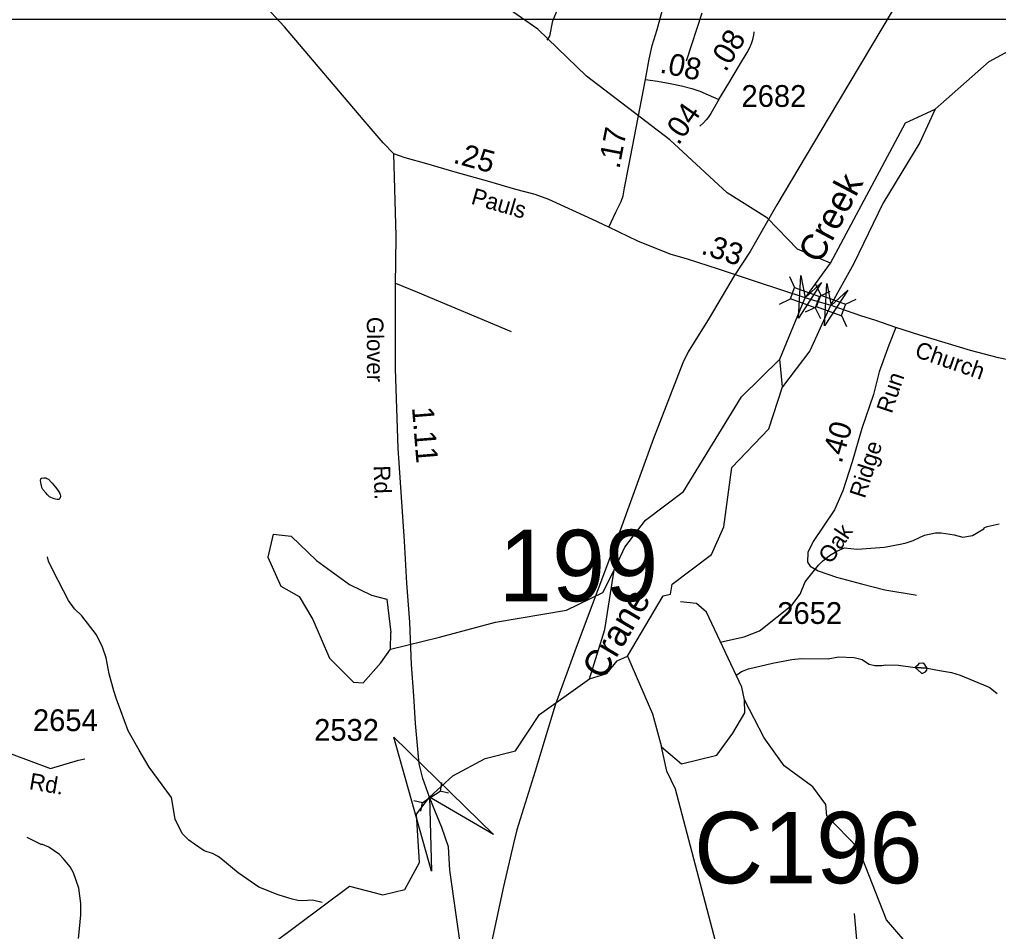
# Model space of a CAD drawing. Extents: x 1473865 to 1648260, y 639067 to 773536.
# Drawn here: x 1555587 to 1561206, y 673439 to 678674 of the extents above; entities that cross this region are included whole.
import ezdxf

# ---------------------------------------------------------------- set-up
doc = ezdxf.new("R2010")
doc.units = 0
for name, color, linetype in [('Exist Hydrographic Creek Single Shore', 7, 'Continuous'), ('Exist Hydrographic Creek Single Shore Label', 7, 'Continuous'), ('Exist Hydrographic Misc Water Feature', 7, 'Continuous'), ('Exist Road Non-System Type 51', 7, 'Continuous'), ('Exist Road Secondary Mileage Hundredths English Label', 7, 'Continuous'), ('Exist Road Secondary Structure Culvert Attributed CELL', 7, 'Continuous'), ('Exist Road Secondary Structure Culvert CELL', 7, 'Continuous'), ('Exist Road Secondary Structure Culvert Number Label', 7, 'Continuous'), ('Exist Road Secondary Structure Standard Bridge Attributed CELL', 7, 'Continuous'), ('Exist Road Secondary Structure Standard Bridge CELL', 7, 'Continuous'), ('Exist Road Secondary Structure Standard Bridge Number Label', 7, 'Continuous'), ('Exist Road Secondary Type 51 Attributed', 7, 'Continuous'), ('Exist Road Secondary Type 51 Label', 7, 'Continuous'), ('Exist Road Secondary Type 51 Number Label', 7, 'Continuous'), ('Exist Utilities Electrical Transmission Line', 7, 'Continuous'), ('Map Preparation Inset Cut Line', 7, 'Continuous')]:
    doc.layers.add(name, color=color, linetype=linetype)

msp = doc.modelspace()

# ---------------------------------------------------------------- linework, layer by layer
at = {"layer": 'Exist Hydrographic Creek Single Shore'}
for points in [[(1560242.5, 677276.1), (1560671.6, 678081.5), (1560841.9, 678160.2), (1561151.5, 678432.8), (1561361.6, 678546.7), (1561438.6, 678676.5), (1561493.6, 679010.1), (1561770.6, 679122.7), (1562006.6, 679295.2), (1562015.6, 679354.1), (1562183.6, 679459)], [(1560841.9, 678160.2), (1560753.8, 677968), (1560542.4, 677617.1), (1560375.2, 677274.4), (1560241.2, 677032.8), (1560123, 676772.7), (1559965.5, 676566)], [(1559951.6, 676723.9), (1560094, 677072.3), (1560242.5, 677276.1)], [(1559323.5, 675374.4), (1559332.5, 675433.3), (1559559.5, 675602.6), (1559629.5, 675762.1), (1559675.6, 676102.5), (1559887.5, 676324.7), (1559965.5, 676566), (1559951.6, 676723.9)], [(1559076.5, 675018.3), (1559281.6, 675365.4), (1559323.5, 675374.4)], [(1558857.5, 674888.1), (1558958.5, 674918.9), (1559017.4, 674993.2), (1559076.5, 675018.3)], [(1558259.5, 674430.8), (1558434.5, 674476.5), (1558571.5, 674683.8), (1558857.5, 674888.1)], [(1560304.5, 669456), (1560297.4, 669574.3), (1560160.4, 669885.6), (1559956.5, 670145.7), (1559858.5, 670331.6), (1559703.5, 670548.1), (1559570.5, 671177.7), (1559432.5, 671420.1), (1559393.4, 671588.3), (1559412.5, 671755.3), (1559472.5, 671878.8), (1559492.5, 672121.3), (1559563.5, 672402.2), (1559594.5, 672792.2), (1559601.4, 673310.7), (1559351.6, 674255.1), (1559302.9, 674358.3), (1559271.4, 674498.8)], [(1555070.4, 671875.8), (1555263.5, 671947.4), (1555572.5, 671960.9), (1555791.5, 672114), (1555983.4, 672146.2), (1556110.4, 672261.8), (1556286.5, 672333.7), (1556363.5, 672466.8), (1556399.4, 672646.6), (1556526.5, 672811.5), (1556578.5, 672928.5), (1556746.5, 673017.1), (1556823.5, 673159.9), (1557043.4, 673372.1), (1557481.5, 673698.1), (1557672.5, 673648.3), (1557798.5, 673678.6), (1557883.5, 673834.4), (1557865.7, 674112.6), (1557939.2, 674210.1), (1558074.5, 674332.8), (1558259.5, 674430.8)]]:
    msp.add_lwpolyline(points, dxfattribs=at)
at = {"layer": 'Exist Hydrographic Misc Water Feature'}
for p, q in [((1560796, 674949.9), (1560728, 674954.7)), ((1560728, 674954.7), (1560796, 674949.9))]:
    msp.add_line(p, q, dxfattribs=at)
for points in [[(1560242.5, 677276.1), (1560052.6, 677355.4), (1559879.6, 677532.8), (1559648.5, 677678.6), (1559319.5, 677984), (1558841.5, 678348.1), (1558561.5, 678619.6), (1558281.5, 678815.7), (1557751.6, 679066), (1557603.5, 679223.3), (1557367.6, 679628.5), (1557032.5, 680107.9), (1556835.6, 680318.7), (1556754.6, 680461.5), (1556400.6, 680793.6), (1556269.5, 680960.4), (1556022.6, 681182)], [(1558615.6, 678555.7), (1558631.3, 678579.5), (1558648.3, 678667.3), (1558685.3, 678758.8), (1558698.9, 678902.7), (1558691.8, 678986.8), (1558685.9, 678988.9), (1558668.3, 679035), (1558641.5, 679133.4), (1558634, 679183.5), (1558634.3, 679207.5), (1558649.6, 679327.3), (1558677, 679451), (1558648.3, 679565.4), (1558607.3, 679663.8), (1558587.8, 679704.1), (1558572, 679728.3), (1558532.5, 679778.7), (1558501, 679825.1)], [(1558857.5, 674888.1), (1558945.5, 675171.9), (1559000.5, 675512.2), (1559060.5, 675645.6), (1559179.5, 675800.7), (1559398.5, 675963.7), (1559731.5, 676508.4), (1559951.6, 676723.9)], [(1555811.6, 675919.4), (1555806.7, 675918.5), (1555803.3, 675918.8), (1555793.3, 675920.2), (1555785.5, 675922.3), (1555766, 675929.9), (1555759.4, 675934.8), (1555747.9, 675946.2), (1555738.4, 675956.6), (1555721.1, 675975.7), (1555715.1, 675987.8), (1555712.8, 675998.1), (1555711.5, 676004.7), (1555707.6, 676026.7), (1555708.9, 676037.8), (1555711.6, 676040.2), (1555715.4, 676041.8), (1555726.8, 676042.4), (1555737.3, 676042.5), (1555744.4, 676039.7), (1555754.1, 676035.2), (1555771.2, 676016.1), (1555774.2, 676012.7), (1555793.9, 675989.2), (1555807.6, 675972.1), (1555817.3, 675953.1), (1555819.3, 675948.2), (1555821.3, 675940.1), (1555821.7, 675934.7), (1555821.1, 675929.6), (1555817.9, 675924.5), (1555811.6, 675919.4)], [(1559617, 675101), (1559745.5, 675130.1), (1559834, 675165.1), (1559842.1, 675171), (1560019.6, 675311), (1560068.3, 675374.4), (1560097.2, 675446.1), (1560172.2, 675541.2), (1560196.5, 675565), (1560236.9, 675596.5), (1560277.2, 675622), (1560321.4, 675641.5), (1560394.9, 675633.6), (1560551.5, 675644.8), (1560651.8, 675663.6), (1560675.8, 675669.4), (1560716, 675682.9), (1560780.4, 675714.1), (1560844.6, 675727.4), (1560876.6, 675727), (1560952.5, 675716.1), (1561001.9, 675702), (1561056.5, 675711), (1561121, 675750.2), (1561123, 675756.2), (1561141.1, 675764), (1561209.3, 675779.2)], [(1557043.3, 675720.1), (1557012.8, 675587.5), (1557086.3, 675421.9), (1557192.1, 675362.1), (1557270.2, 675228.7), (1557366.7, 675007.9), (1557504.6, 674869.9), (1557559.8, 674865.3), (1557660.9, 674980.3), (1557716.1, 675058.5), (1557718.3, 675155.8)], [(1557043.3, 675720.1), (1557146.7, 675708.7), (1557292.2, 675568.3), (1557480.2, 675430.5), (1557607.2, 675369.6), (1557694.6, 675345.7), (1557718.3, 675155.8)], [(1557324.1, 673604.1), (1557267.8, 673618.9), (1557211.8, 673613.5), (1557183.8, 673615.8), (1557151.9, 673624.2), (1557072.1, 673649.2), (1556960.6, 673692.5), (1556841.4, 673775.8), (1556742.3, 673857), (1556726.4, 673869.2), (1556694.5, 673885.6), (1556646.7, 673902.1), (1556591.1, 673938.8), (1556559.4, 673963.1), (1556519.8, 674001.6), (1556480.6, 674084.1), (1556459.6, 674206.7), (1556331.9, 674381.9), (1556312.3, 674414), (1556272.9, 674478.5), (1556210.2, 674591.3), (1556168.1, 674704.9), (1556144.2, 674772.1), (1556128.7, 674820.3), (1556101.8, 674918.6), (1556084.8, 675008.8), (1556063.5, 675071), (1556028.2, 675141.5), (1555945.4, 675250.4), (1555901.8, 675291), (1555868.4, 675339.3), (1555780.2, 675508.4), (1555752.8, 675564.7), (1555747.1, 675588.8)], [(1557716.1, 675058.5), (1557996.5, 675127.5), (1558318.2, 675214.9), (1558727.3, 675283.9), (1558934.1, 675385.1), (1559000.5, 675512.2)], [(1561348.5, 672451.5), (1561183.5, 672618.9), (1561152.5, 672754.1), (1560922.5, 672975.5), (1560825.5, 673200.6), (1560563.4, 673504.6), (1560402.5, 673914.8), (1560221.5, 674102.4), (1560214.5, 674168.1), (1560140.5, 674268.1), (1559975.5, 674389.6), (1559861.5, 674549.4), (1559748.5, 674768.4), (1559732.5, 674840.9), (1559530.5, 675271.7), (1559472.5, 675322.1), (1559380.5, 675330.5)], [(1559076.5, 675018.3), (1559219.8, 674688), (1559271.4, 674498.8), (1559385.9, 674401.3), (1559589.3, 674450.1), (1559681, 674576.2), (1559749.7, 674693.7), (1559748.5, 674768.4)], [(1559703.3, 674911.6), (1559731.3, 674930.3), (1559771.5, 674945.8), (1559907.9, 674978.2), (1560020.2, 674999), (1560074.3, 675006.3), (1560228.3, 675004.5), (1560288.5, 675015.8), (1560378.5, 675010.7), (1560400.4, 675006.5), (1560424.3, 675000.2), (1560448.2, 674981.9), (1560464.1, 674973.8), (1560496, 674965.4), (1560536, 674964.9), (1560560.1, 674968.7), (1560632, 674967.8), (1560728, 674954.7)], [(1560796, 674949.9), (1560782.2, 674974), (1560772.3, 674978.2), (1560748.2, 674976.5), (1560742.1, 674966.5), (1560728, 674954.7)], [(1560728, 674954.7), (1560763.6, 674922.3), (1560771.7, 674922.2), (1560787.7, 674930), (1560793.8, 674937.9), (1560796, 674949.9)], [(1560796, 674949.9), (1560867.7, 674936), (1560935.7, 674925.8), (1560985.7, 674909.5), (1561142.9, 674845.8), (1561158.8, 674837.6), (1561198.5, 674805.2)], [(1555924.9, 673398.5), (1555931.5, 673454.4), (1555938.4, 673534.3), (1555939.1, 673598.3), (1555928, 673686.5), (1555897.1, 673774.8), (1555877.9, 673809.1), (1555839.9, 673855.5), (1555816.2, 673879.8), (1555754.7, 673922.5), (1555718.8, 673936.9), (1555710.8, 673937), (1555631.2, 673978)]]:
    msp.add_lwpolyline(points, dxfattribs=at)
at = {"layer": 'Exist Road Non-System Type 51'}
for points in [[(1557744.5, 677160.4), (1557871.1, 677109.1), (1558408.2, 676882.4)], [(1560378.4, 673541.8), (1560393, 673371.8), (1560394.1, 673254), (1560441.1, 673130.2), (1560488, 673013), (1560509.1, 672931.7)]]:
    msp.add_lwpolyline(points, dxfattribs=at)
at = {"layer": 'Exist Road Secondary Structure Culvert Attributed CELL'}
msp.add_lwpolyline([(1557951.9, 673783.9), (1557734.7, 674553.9), (1558307.8, 673995.7), (1557939.2, 674210.1)], close=True, dxfattribs=at)
at = {"layer": 'Exist Road Secondary Structure Culvert CELL'}
for p, q in [((1558009.8, 674294.1), (1558000.7, 674244.2)), ((1557899.3, 674178.2), (1558000.7, 674244.2)), ((1558050, 674232.3), (1558000.7, 674244.2)), ((1557849.9, 674190.1), (1557899.3, 674178.2)), ((1557890.1, 674128.3), (1557899.3, 674178.2))]:
    msp.add_line(p, q, dxfattribs=at)
at = {"layer": 'Exist Road Secondary Structure Standard Bridge Attributed CELL'}
for points in [[(1560190.9, 677164.4), (1560057.4, 676960.4), (1560071, 677203.9), (1560095.5, 677076.2)], [(1560340.6, 677119.8), (1560207, 676915.8), (1560220.7, 677159.3), (1560245.1, 677031.6)]]:
    msp.add_lwpolyline(points, close=True, dxfattribs=at)
at = {"layer": 'Exist Road Secondary Structure Standard Bridge CELL'}
for p, q in [((1560006.5, 677198.5), (1560035.8, 677136.1)), ((1560156.1, 677153.9), (1560185.4, 677091.5)), ((1560177.9, 677084.6), (1560240.3, 677113.9)), ((1559949.5, 677040.3), (1560011.9, 677069.7)), ((1560099.1, 676995.7), (1560161.5, 677025)), ((1560154.5, 677019.7), (1560183.9, 676957.2)), ((1560327.5, 677039.9), (1560389.9, 677069.3)), ((1560304.1, 676975), (1560333.5, 676912.6))]:
    msp.add_line(p, q, dxfattribs=at)
for points in [[(1560035.8, 677136.1), (1560178, 677084.9), (1560154.1, 677018.5), (1560011.9, 677069.7)], [(1560185.4, 677091.5), (1560327.6, 677040.2), (1560303.7, 676973.8), (1560161.5, 677025)]]:
    msp.add_lwpolyline(points, close=True, dxfattribs=at)
at = {"layer": 'Exist Road Secondary Type 51 Attributed'}
for points in [[(1557735.9, 677902.4), (1557674.9, 677966.6), (1557559, 678099.9), (1557107.4, 678631.6), (1556904.1, 678851.7), (1556761.6, 679016.1), (1556560.3, 679246.3), (1556403.8, 679421.7), (1556324.5, 679498.5), (1556225.3, 679587.4), (1556137.8, 679646.2), (1556056.1, 679693.1), (1555960.8, 679768), (1555680.3, 679956.6), (1555527.2, 680066.1), (1555411.7, 680135.1)], [(1559180.2, 678330.8), (1559200.1, 678446.7), (1559218.7, 678524.6), (1559245.9, 678616.1), (1559302.8, 678822.7), (1559364.7, 679058.9), (1559394.6, 679167.9)], [(1559600, 678214.9), (1559657.9, 678309.1), (1559720, 678412.1), (1559763.3, 678485.2), (1559778.2, 678513.5), (1559788.5, 678537.1), (1559796.3, 678559.9), (1559802.6, 678583.5), (1559804.2, 678603.9)], [(1558969.6, 677481.8), (1559009, 677567.4), (1559039.7, 677628.6), (1559051.6, 677662.6), (1559060.1, 677708.5), (1559083.9, 677834.3), (1559180.2, 678330.8)], [(1559180.2, 678330.8), (1559249.6, 678320.5), (1559321.4, 678306.9), (1559387, 678293.3), (1559446.4, 678278.5), (1559492.2, 678262.4), (1559540.4, 678241.4), (1559600, 678214.9)], [(1559600, 678214.9), (1559555.6, 678135.4), (1559539.1, 678111.8), (1559528.1, 678098.5), (1559513.2, 678082), (1559491.9, 678062.3)], [(1558421.7, 672101.1), (1558254.7, 672692.9), (1558135.5, 673238), (1558056.4, 673791), (1558049.7, 673925), (1558010.9, 674035.3), (1557970.5, 674132.9), (1557939.2, 674210.1), (1557902.5, 674316.9), (1557879.9, 674400.7), (1557859.9, 674633), (1557849.3, 674791.1), (1557837, 674971.2), (1557827.1, 675213.4), (1557809, 675437.6), (1557797.3, 675679.8), (1557760, 676212.4), (1557744, 676668.5), (1557744.5, 677160.4), (1557747.3, 677276.8), (1557748.8, 677432.8), (1557735.9, 677902.4)], [(1558969.6, 677481.8), (1558876.4, 677526.4), (1558625.6, 677640.5), (1558546.5, 677669.3), (1558435.7, 677698.1), (1558286.1, 677742.7), (1558086.9, 677797.3), (1557924.4, 677844.8), (1557800.7, 677880.8), (1557735.9, 677902.4)], [(1560095.5, 677076.2), (1559823.6, 677165.5), (1559599.2, 677241.8), (1559420.1, 677297.5), (1559322.3, 677327.7), (1559135.3, 677402.5), (1558969.6, 677481.8)], [(1560245.1, 677031.6), (1560164.5, 677054.6), (1560095.5, 677076.2)], [(1560616.7, 676907), (1560501.2, 676946.7), (1560415.1, 676973.5), (1560245.1, 677031.6)], [(1560616.7, 676907), (1560576.4, 676804.8), (1560521.1, 676650.9), (1560487.9, 676521.1), (1560422.1, 676325.7), (1560366.4, 676134.1), (1560313.1, 675968.5), (1560264, 675859.1), (1560142.3, 675678), (1560111.8, 675614.4), (1560109.3, 675558.4), (1560125, 675536.3), (1560170.7, 675509.8), (1560276.6, 675472.8), (1560420.3, 675433.5), (1560554.1, 675400.2), (1560727.8, 675370.7), (1560735.2, 675368.7)], [(1562515, 676721.9), (1562355.9, 676708.1), (1561916.4, 676685.5), (1561701.7, 676681.8), (1561427.5, 676690.4), (1561302.9, 676711.3), (1561206, 676732.1), (1561044.4, 676773.6), (1560755.1, 676862.2), (1560616.7, 676907)], [(1554841.1, 674571.4), (1555118.4, 674563.8), (1555327.6, 674528.9), (1555538.2, 674457.6), (1555765.5, 674374.2), (1555924.6, 674422.7), (1555962.5, 674428.8)]]:
    msp.add_lwpolyline(points, dxfattribs=at)
at = {"layer": 'Exist Road Secondary Type 51 Number Label'}
msp.add_line((1559415.9, 678436.7), (1559505.6, 678711.8), dxfattribs=at)
at = {"layer": 'Exist Utilities Electrical Transmission Line'}
msp.add_lwpolyline([(1560594.8, 678721.8), (1560228.6, 678106.7), (1559932.9, 677611), (1559780, 677342.5), (1559688.3, 677203.5), (1559545.7, 676959.1), (1559425.6, 676766.4), (1559394.9, 676702.8), (1559226.2, 676268.6), (1559036.6, 675746.6), (1558781.4, 675069.2), (1558661.9, 674738.5), (1558545.7, 674359.6), (1558442.1, 674022.8), (1558421.3, 673942.9), (1558364.7, 673697.6), (1558257.3, 673196.7)], dxfattribs=at)
at = {"layer": 'Map Preparation Inset Cut Line'}
for points in [[(1530807.2, 678673.7), (1530807.2, 722115.9), (1605695.7, 722115.9), (1605695.7, 695030), (1593323.3, 695030), (1593323.3, 678673.7), (1530807.2, 678673.7)], [(1544130.8, 639067.3), (1606587.1, 639067.3), (1606587.1, 678673.7), (1544130.8, 678673.7), (1544130.8, 639067.3)]]:
    msp.add_lwpolyline(points, dxfattribs=at)

# ---------------------------------------------------------------- texts
at = {"layer": 'Exist Hydrographic Creek Single Shore Label'}
for s, rotation, p in [('Creek', 61.9537, (1560181.6, 677266.4)), ('Crane', 59.4273, (1558936.6, 674878.2))]:
    msp.add_text(s, height=150, rotation=rotation, dxfattribs=at).set_placement(p)
at = {"layer": 'Exist Road Secondary Mileage Hundredths English Label'}
for s, rotation, p in [('.08', 58.8924, (1559639.5, 678368.2)), ('.08', 348.2823, (1559257.2, 678370.5)), ('.04', 54.9925, (1559368.8, 677947.5)), ('.17', 79.0212, (1559029.5, 677812.5)), ('.25', 344.6869, (1558070.5, 677852.8)), ('.33', 341.8257, (1559493.2, 677331.1)), ('1.11', 274.6083, (1557839.3, 676447.1)), ('.40', 73.789, (1560304.5, 676121))]:
    msp.add_text(s, height=125, rotation=rotation, dxfattribs=at).set_placement(p)
at = {"layer": 'Exist Road Secondary Structure Culvert Number Label'}
msp.add_text('C196', height=410.1, dxfattribs=at).set_placement((1559458.6, 673715.2))
at = {"layer": 'Exist Road Secondary Structure Standard Bridge Number Label'}
msp.add_text('199', height=410.1, dxfattribs=at).set_placement((1558338.2, 675334.3))
at = {"layer": 'Exist Road Secondary Type 51 Label'}
for s, rotation, p in [('Pauls', 343.9518, (1558173.4, 677617.6)), ('Glover', 270.1305, (1557580.4, 676967)), ('Church', 340.8284, (1560719.4, 676739.6)), ('Run', 71.392, (1560593, 676407.7)), ('Ridge', 72.1373, (1560438.7, 675920.3)), ('Rd.', 272.0082, (1557618.9, 676112.6)), ('Oak', 56.085, (1560244, 675542.9)), ('Rd.', 350.3634, (1555638, 674256.1))]:
    msp.add_text(s, height=95, rotation=rotation, dxfattribs=at).set_placement(p)
at = {"layer": 'Exist Road Secondary Type 51 Number Label'}
for s, p in [('2682', (1559730.9, 678172.7)), ('2652', (1559936.4, 675204.3)), ('2654', (1555664, 674588.8)), ('2532', (1557278, 674533.1))]:
    msp.add_text(s, height=125, dxfattribs=at).set_placement(p)

doc.saveas('drawing.dxf')
